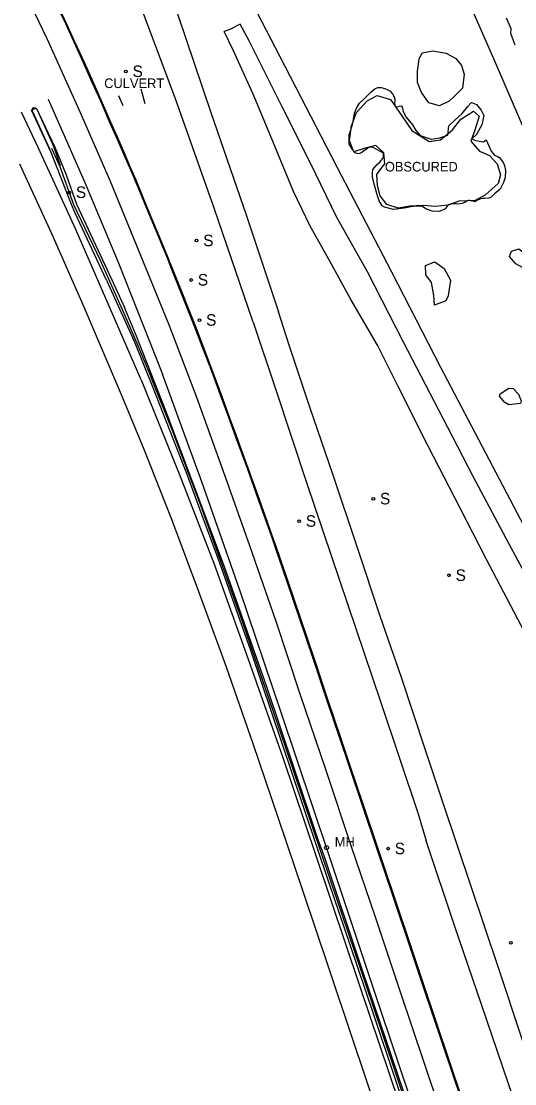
# Model space of a CAD drawing. Extents: x 368532 to 392481, y 10654822 to 10676899.
# Drawn here: x 377470 to 377726, y 10662494 to 10663046 of the extents above; entities that cross this region are included whole.
import ezdxf

# ---------------------------------------------------------------- set-up
doc = ezdxf.new("R2010")
doc.units = 0
for name, color, linetype in [('p_drainage culvert', 7, 'Continuous'), ('p_dtm obscured area', 7, 'Continuous'), ('p_railroad rr control', 7, 'Continuous'), ('p_road - paved curb', 7, 'Continuous'), ('p_road conc barrier', 7, 'Continuous'), ('p_road dirt road', 7, 'Continuous'), ('p_road guard rails', 7, 'Continuous'), ('p_road paint stripe', 7, 'Continuous'), ('p_structure sign', 7, 'Continuous'), ('p_utility manhole', 7, 'Continuous'), ('p_veg woods', 7, 'Continuous')]:
    doc.layers.add(name, color=color, linetype=linetype)

msp = doc.modelspace()

# ---------------------------------------------------------------- linework, layer by layer
at = {"layer": 'p_drainage culvert'}
for p, q in [((377531.8, 10663011.14), (377533.76, 10663003.58)), ((377522.55, 10663002.38), (377520.28, 10663007.6))]:
    msp.add_line(p, q, dxfattribs=at)
at = {"layer": 'p_dtm obscured area'}
msp.add_lwpolyline([(377726.43, 10663033.97), (377724.75, 10663038.16), (377724.08, 10663040.01), (377724.21, 10663042.39), (377723.19, 10663044.85), (377721.77, 10663047.88)], dxfattribs=at)
msp.add_lwpolyline([(377657.26, 10662950.44), (377655.61, 10662953.02), (377654.77, 10662955.59), (377653.71, 10662959.19), (377652.87, 10662962.35), (377652.22, 10662965.49), (377652.22, 10662967.62), (377652.33, 10662969.26), (377653.42, 10662970.48), (377654.62, 10662971.9), (377655.88, 10662972.97), (377656.79, 10662974.12), (377657, 10662974.45), (377657.54, 10662975.12), (377657.98, 10662975.35), (377657.92, 10662977.72), (377652.19, 10662980.83), (377650.5, 10662980.83), (377649.07, 10662979.9), (377647.61, 10662978.94), (377646.16, 10662977.87), (377644.69, 10662977.42), (377643.14, 10662978), (377641.71, 10662979.65), (377640.04, 10662982.53), (377640.13, 10662987.31), (377641.88, 10662993.29), (377642.81, 10662998.58), (377644.22, 10663001.81), (377645.45, 10663003.72), (377647.88, 10663006.02), (377649.29, 10663007.44), (377651.28, 10663009.52), (377653.31, 10663011.15), (377654.92, 10663011.87), (377655.78, 10663011.99), (377656.72, 10663011.87), (377657.92, 10663011.59), (377658.55, 10663011.45), (377660.12, 10663010.75), (377661.45, 10663009.96), (377662.58, 10663008.71), (377663.34, 10663007.44), (377663.83, 10663005.8), (377663.82, 10663004.65), (377663.68, 10663003.88), (377663.78, 10663002.77), (377664.15, 10663001.92), (377665.4, 10663002.09), (377665.99, 10663002.22), (377667.06, 10663002.43), (377667.44, 10663002.15), (377667.76, 10663001.22), (377668.02, 10663000.07), (377668.17, 10662999.53), (377668.5, 10662998.83), (377669.61, 10662996.55), (377672.93, 10662992.45), (377674.66, 10662989.62), (377677, 10662986.99), (377682.7, 10662984.99), (377687.17, 10662985.67), (377691.32, 10662987.09), (377691.86, 10662991.94), (377695.18, 10662995.08), (377698.74, 10662998.45), (377701.77, 10663002.12), (377703.68, 10663004.09), (377706.3, 10663003.02), (377708.75, 10663000.16), (377710.1, 10662997.38), (377708.96, 10662992.44), (377706.21, 10662987.56), (377703.74, 10662985.29), (377705.75, 10662984.34), (377709.9, 10662983.71), (377711.31, 10662984.65), (377712, 10662983.15), (377713.8, 10662978.82), (377715.7, 10662976.54), (377717, 10662976.19), (377718.42, 10662975.33), (377720.09, 10662973.02), (377720.76, 10662971.45), (377721.38, 10662968.86), (377721.2, 10662965.09), (377720.26, 10662962.46), (377718.49, 10662959.1), (377715.68, 10662956.67), (377713.9, 10662954.99), (377712.69, 10662954.38), (377710.48, 10662954.26), (377709.19, 10662954.14), (377708.33, 10662954.03), (377706.48, 10662953.18), (377705.49, 10662952.57), (377704.98, 10662952.59), (377703.83, 10662953.02), (377703.27, 10662953.05), (377702.62, 10662953.17), (377701.85, 10662953.14), (377700.95, 10662952.74), (377700.16, 10662952.16), (377698.84, 10662951.6), (377697.82, 10662951.42), (377697.06, 10662951.25), (377695.93, 10662951.46), (377694.78, 10662951.45), (377693.84, 10662951.45), (377693.13, 10662951.46), (377691.72, 10662950.94), (377691.18, 10662950.59), (377690.81, 10662950.06), (377690.67, 10662949.78), (377689.96, 10662948.85), (377686.99, 10662947.55), (377683.16, 10662947.61), (377680.2, 10662948.7), (377678.03, 10662950.06), (377674.8, 10662950.22), (377672.03, 10662949.89), (377668.72, 10662949.27), (377663.14, 10662948.51), (377658.5, 10662949.8)], close=True, dxfattribs=at)
at = {"layer": 'p_railroad rr control'}
for points in [[(377533.14, 10663389.06), (377560.85, 10663341.04), (377588.79, 10663290.47), (377613.7, 10663243.12), (377634.41, 10663202.3), (377655.63, 10663158.5), (377673.78, 10663119.33), (377695.32, 10663071.97), (377715.09, 10663027.07), (377741.59, 10662965.55)], [(377447.27, 10663322.87), (377465.08, 10663281.81), (377482.07, 10663241.61), (377497.54, 10663201.82), (377506.53, 10663177.13), (377520.96, 10663136.85), (377536.83, 10663091.36), (377550.94, 10663049.62), (377568.16, 10662998.98), (377586.49, 10662945.67), (377603.25, 10662895.25)], [(377590.08, 10662889.98), (377569.68, 10662949.66), (377549.68, 10663006.06), (377531.81, 10663054.07), (377515.57, 10663096.65), (377498.35, 10663138.59), (377483.09, 10663175.15), (377475.05, 10663194.09), (377459.92, 10663228.21), (377440.7, 10663269.48), (377423.08, 10663306.75), (377415.62, 10663322.06)], [(377662.32, 10662915.92), (377633.85, 10662970.55), (377604.16, 10663027.92), (377573.43, 10663087.11), (377541.68, 10663147.47), (377509.84, 10663208.39), (377479.66, 10663266.26), (377460.16, 10663303.76), (377455.02, 10663314.64)], [(377872.51, 10662512.94), (377854.1, 10662547.75), (377833.48, 10662587.51), (377809.12, 10662634), (377784.88, 10662680.38), (377759.49, 10662728.97), (377734.76, 10662776.63), (377712.8, 10662818.59), (377687.78, 10662866.46), (377662.32, 10662915.92)], [(377688.74, 10662640.45), (377679.61, 10662667.96), (377667.24, 10662705.2), (377656.14, 10662737.21), (377644.41, 10662772.65), (377631.82, 10662810.45), (377619.68, 10662845.83), (377608.78, 10662877.94), (377603.25, 10662895.25)], [(377590.08, 10662889.98), (377601.86, 10662854.83), (377617.89, 10662806.63), (377634.98, 10662755.84), (377656.27, 10662692.73), (377675.99, 10662634.43), (377680.14, 10662620.39)], [(377788.33, 10662339.5), (377779.16, 10662370.49), (377766.4, 10662408.93), (377751.86, 10662451.84), (377740.64, 10662485.75), (377729.57, 10662518.37), (377717.5, 10662554.85), (377703.53, 10662596.62), (377688.74, 10662640.45)], [(377857.56, 10662092.99), (377838.98, 10662148.02), (377820.16, 10662203.49), (377802.83, 10662255.08), (377786.31, 10662304.43), (377769.63, 10662354.52), (377752.35, 10662405.57), (377741.43, 10662438), (377734.41, 10662460.71), (377722.68, 10662494.64), (377708.8, 10662535.35), (377695.06, 10662575.82), (377680.14, 10662620.39)]]:
    msp.add_lwpolyline(points, dxfattribs=at)
at = {"layer": 'p_road - paved curb'}
for p, q in [((377492.67, 10663044.93), (377487.72, 10663055.45)), ((377492.81, 10663044.99), (377487.86, 10663055.51)), ((377493.12, 10663045.14), (377488.17, 10663055.66)), ((377497.06, 10663035.53), (377492.67, 10663044.93)), ((377497.2, 10663035.59), (377492.81, 10663044.99)), ((377497.51, 10663035.74), (377493.12, 10663045.14)), ((377502.08, 10663024.73), (377497.2, 10663035.59)), ((377502.4, 10663024.88), (377497.51, 10663035.74)), ((377501.94, 10663024.67), (377497.06, 10663035.53)), ((377506.48, 10663014.59), (377501.94, 10663024.67)), ((377506.62, 10663014.65), (377502.08, 10663024.73)), ((377506.94, 10663014.79), (377502.4, 10663024.88)), ((377510.89, 10663004.75), (377506.48, 10663014.59)), ((377511.03, 10663004.81), (377506.62, 10663014.65)), ((377511.35, 10663004.95), (377506.94, 10663014.79)), ((377515.36, 10662994.42), (377510.89, 10663004.75)), ((377515.5, 10662994.48), (377511.03, 10663004.81)), ((377515.82, 10662994.62), (377511.35, 10663004.95)), ((377474.98, 10663000.1), (377477.41, 10663001.4)), ((377483.87, 10662980.75), (377474.98, 10663000.1)), ((377477.41, 10663001.4), (377486.98, 10662980.96)), ((377519.43, 10662985.2), (377515.36, 10662994.42)), ((377519.57, 10662985.26), (377515.5, 10662994.48)), ((377519.89, 10662985.4), (377515.82, 10662994.62)), ((377485.19, 10662978.18), (377483.87, 10662980.75)), ((377486.98, 10662980.96), (377492.91, 10662966.45)), ((377522.73, 10662977.66), (377519.43, 10662985.2)), ((377522.87, 10662977.72), (377519.57, 10662985.26)), ((377523.19, 10662977.86), (377519.89, 10662985.4)), ((377495.62, 10662951.14), (377485.19, 10662978.18)), ((377525.97, 10662970.11), (377522.73, 10662977.66)), ((377526.11, 10662970.17), (377522.87, 10662977.72)), ((377526.43, 10662970.31), (377523.19, 10662977.86)), ((377528.2, 10662965.05), (377525.97, 10662970.11)), ((377528.34, 10662965.11), (377526.11, 10662970.17)), ((377528.66, 10662965.25), (377526.43, 10662970.31)), ((377492.91, 10662966.45), (377498.24, 10662951.23)), ((377528.97, 10662963.26), (377528.2, 10662965.05)), ((377529.11, 10662963.32), (377528.34, 10662965.11)), ((377529.43, 10662963.46), (377528.66, 10662965.25)), ((377529.6, 10662961.76), (377528.97, 10662963.26)), ((377529.74, 10662961.82), (377529.11, 10662963.32)), ((377530.06, 10662961.95), (377529.43, 10662963.46)), ((377534.83, 10662949.08), (377529.6, 10662961.76)), ((377534.97, 10662949.14), (377529.74, 10662961.82)), ((377535.29, 10662949.27), (377530.06, 10662961.95)), ((377497.57, 10662946.61), (377495.62, 10662951.14)), ((377498.24, 10662951.23), (377516.75, 10662911.94)), ((377538.47, 10662940.32), (377534.83, 10662949.08)), ((377538.61, 10662940.38), (377534.97, 10662949.14)), ((377538.93, 10662940.51), (377535.29, 10662949.27)), ((377513.91, 10662911.82), (377497.57, 10662946.61)), ((377542.25, 10662931.12), (377538.47, 10662940.32)), ((377542.39, 10662931.18), (377538.61, 10662940.38)), ((377542.71, 10662931.31), (377538.93, 10662940.51)), ((377545.52, 10662923.15), (377542.25, 10662931.12)), ((377545.66, 10662923.21), (377542.39, 10662931.18)), ((377545.98, 10662923.34), (377542.71, 10662931.31)), ((377548.46, 10662915.93), (377545.52, 10662923.15)), ((377548.6, 10662915.99), (377545.66, 10662923.21)), ((377548.92, 10662916.12), (377545.98, 10662923.34)), ((377552.05, 10662906.92), (377548.46, 10662915.93)), ((377552.19, 10662906.98), (377548.6, 10662915.99)), ((377552.51, 10662907.1), (377548.92, 10662916.12)), ((377513.91, 10662911.82), (377528.23, 10662880.01)), ((377516.75, 10662911.94), (377523.27, 10662897.64)), ((377556.35, 10662895.98), (377552.05, 10662906.92)), ((377556.49, 10662896.04), (377552.19, 10662906.98)), ((377556.81, 10662896.16), (377552.51, 10662907.1)), ((377529.51, 10662882.6), (377523.27, 10662897.64)), ((377559.8, 10662887.35), (377556.35, 10662895.98)), ((377559.94, 10662887.41), (377556.49, 10662896.04)), ((377560.27, 10662887.53), (377556.81, 10662896.16)), ((377564.03, 10662876.51), (377559.8, 10662887.35)), ((377564.17, 10662876.56), (377559.94, 10662887.41)), ((377564.5, 10662876.69), (377560.27, 10662887.53)), ((377544.69, 10662843.94), (377529.51, 10662882.6)), ((377528.23, 10662880.01), (377537.66, 10662856.8)), ((377568.61, 10662864.5), (377564.03, 10662876.51)), ((377568.75, 10662864.55), (377564.17, 10662876.56)), ((377569.08, 10662864.68), (377564.5, 10662876.69)), ((377573.19, 10662852.07), (377568.61, 10662864.5)), ((377573.33, 10662852.12), (377568.75, 10662864.55)), ((377573.66, 10662852.24), (377569.08, 10662864.68)), ((377537.66, 10662856.8), (377555.94, 10662809.99)), ((377577.43, 10662840.45), (377573.19, 10662852.07)), ((377577.57, 10662840.5), (377573.33, 10662852.12)), ((377577.9, 10662840.62), (377573.66, 10662852.24)), ((377575.21, 10662762.85), (377544.69, 10662843.94)), ((377581.18, 10662830.2), (377577.43, 10662840.45)), ((377581.32, 10662830.25), (377577.57, 10662840.5)), ((377581.65, 10662830.37), (377577.9, 10662840.62)), ((377587.12, 10662813.86), (377581.18, 10662830.2)), ((377587.26, 10662813.91), (377581.32, 10662830.25)), ((377587.59, 10662814.03), (377581.65, 10662830.37)), ((377555.94, 10662809.99), (377563.54, 10662789.68)), ((377592.88, 10662797.63), (377587.12, 10662813.86)), ((377593.02, 10662797.68), (377587.26, 10662813.91)), ((377593.35, 10662797.8), (377587.59, 10662814.03)), ((377599.62, 10662778.86), (377592.88, 10662797.63)), ((377599.76, 10662778.91), (377593.02, 10662797.68)), ((377600.09, 10662779.03), (377593.35, 10662797.8)), ((377563.54, 10662789.68), (377571.75, 10662767.23)), ((377601.6, 10662773.13), (377599.62, 10662778.86)), ((377601.74, 10662773.18), (377599.76, 10662778.91)), ((377602.07, 10662773.29), (377600.09, 10662779.03)), ((377607.83, 10662755.01), (377601.6, 10662773.13)), ((377607.97, 10662755.06), (377601.74, 10662773.18)), ((377608.3, 10662755.17), (377602.07, 10662773.29)), ((377571.75, 10662767.23), (377588.68, 10662719.55)), ((377597.26, 10662700.45), (377575.21, 10662762.85)), ((377617.67, 10662725.87), (377607.83, 10662755.01)), ((377617.81, 10662725.92), (377607.97, 10662755.06)), ((377618.14, 10662726.03), (377608.3, 10662755.17)), ((377621.66, 10662714.12), (377617.67, 10662725.87)), ((377621.8, 10662714.17), (377617.81, 10662725.92)), ((377622.13, 10662714.28), (377618.14, 10662726.03)), ((377588.68, 10662719.55), (377610.44, 10662655.27)), ((377628.68, 10662693.19), (377621.66, 10662714.12)), ((377628.82, 10662693.24), (377621.8, 10662714.17)), ((377629.15, 10662693.35), (377622.13, 10662714.28)), ((377611.68, 10662657.68), (377597.26, 10662700.45)), ((377635.2, 10662673.75), (377628.68, 10662693.19)), ((377635.34, 10662673.8), (377628.82, 10662693.24)), ((377635.67, 10662673.91), (377629.15, 10662693.35)), ((377640.23, 10662658.75), (377635.2, 10662673.75)), ((377640.37, 10662658.8), (377635.34, 10662673.8)), ((377640.7, 10662658.91), (377635.67, 10662673.91)), ((377610.44, 10662655.27), (377629.34, 10662599.02)), ((377623.95, 10662620.96), (377611.68, 10662657.68)), ((377646.82, 10662639.33), (377640.23, 10662658.75)), ((377646.96, 10662639.38), (377640.37, 10662658.8)), ((377647.29, 10662639.49), (377640.7, 10662658.91)), ((377654.98, 10662614.96), (377646.82, 10662639.33)), ((377655.12, 10662615.01), (377646.96, 10662639.38)), ((377655.45, 10662615.12), (377647.29, 10662639.49)), ((377626.98, 10662612.51), (377623.95, 10662620.96)), ((377647.14, 10662552.47), (377626.98, 10662612.51)), ((377662.75, 10662591.88), (377654.98, 10662614.96)), ((377662.89, 10662591.93), (377655.12, 10662615.01)), ((377663.22, 10662592.04), (377655.45, 10662615.12)), ((377629.34, 10662599.02), (377640.16, 10662567.02)), ((377672.08, 10662564.09), (377662.75, 10662591.88)), ((377672.22, 10662564.14), (377662.89, 10662591.93)), ((377672.55, 10662564.25), (377663.22, 10662592.04)), ((377640.16, 10662567.02), (377652.55, 10662530.59)), ((377675.56, 10662553.74), (377672.08, 10662564.09)), ((377675.7, 10662553.79), (377672.22, 10662564.14)), ((377676.03, 10662553.9), (377672.55, 10662564.25)), ((377672.72, 10662477.5), (377647.14, 10662552.47)), ((377679.62, 10662541.67), (377675.56, 10662553.74)), ((377679.76, 10662541.72), (377675.7, 10662553.79)), ((377680.09, 10662541.83), (377676.03, 10662553.9)), ((377683.05, 10662531.49), (377679.62, 10662541.67)), ((377683.19, 10662531.54), (377679.76, 10662541.72)), ((377683.52, 10662531.65), (377680.09, 10662541.83)), ((377652.55, 10662530.59), (377663.76, 10662497.02)), ((377693.96, 10662499), (377683.05, 10662531.49)), ((377694.1, 10662499.05), (377683.19, 10662531.54)), ((377694.43, 10662499.16), (377683.52, 10662531.65)), ((377663.76, 10662497.02), (377676.39, 10662459.41)), ((377698.43, 10662485.72), (377693.96, 10662499)), ((377698.57, 10662485.77), (377694.1, 10662499.05)), ((377698.9, 10662485.88), (377694.43, 10662499.16))]:
    msp.add_line(p, q, dxfattribs=at)
at = {"layer": 'p_road conc barrier'}
for p, q in [((377485.35, 10662980.43), (377489.64, 10662970.87)), ((377489.64, 10662970.87), (377496.72, 10662951.08)), ((377496.72, 10662951.08), (377510.54, 10662922.13)), ((377510.54, 10662922.13), (377522.85, 10662894.63)), ((377522.85, 10662894.63), (377530.2, 10662877.85)), ((377530.2, 10662877.85), (377537.12, 10662861.27)), ((377548, 10662834.03), (377537.12, 10662861.27)), ((377562.92, 10662794.66), (377548, 10662834.03)), ((377584.75, 10662733.81), (377562.92, 10662794.66)), ((377606.96, 10662669.29), (377584.75, 10662733.81)), ((377630.4, 10662599.84), (377606.96, 10662669.29)), ((377652.28, 10662535.04), (377630.4, 10662599.84)), ((377674.04, 10662470.58), (377652.28, 10662535.04))]:
    msp.add_line(p, q, dxfattribs=at)
at = {"layer": 'p_road dirt road'}
for p, q in [((377577.94, 10663042.05), (377574.99, 10663041.03)), ((377583.31, 10663044.85), (377577.94, 10663042.05)), ((377588.21, 10663035.78), (377583.31, 10663044.85)), ((377579.87, 10663031), (377574.99, 10663041.03)), ((377605.17, 10663001.8), (377588.21, 10663035.78)), ((377590.2, 10663008.38), (377579.87, 10663031)), ((377599.36, 10662986.5), (377590.2, 10663008.38)), ((377620.16, 10662972.29), (377605.17, 10663001.8)), ((377611.13, 10662957.92), (377599.36, 10662986.5)), ((377633.41, 10662944.72), (377620.16, 10662972.29)), ((377619.59, 10662940.17), (377611.13, 10662957.92)), ((377649.55, 10662916.04), (377633.41, 10662944.72)), ((377630.93, 10662920.17), (377619.59, 10662940.17)), ((377640.99, 10662901.79), (377630.93, 10662920.17)), ((377668.31, 10662879.62), (377649.55, 10662916.04)), ((377654.7, 10662877.96), (377640.99, 10662901.79)), ((377665.55, 10662856.51), (377654.7, 10662877.96)), ((377691.43, 10662835.15), (377668.31, 10662879.62)), ((377681.07, 10662825.55), (377665.55, 10662856.51)), ((377704.55, 10662809.8), (377691.43, 10662835.15)), ((377697.83, 10662793.34), (377681.07, 10662825.55)), ((377723.1, 10662774.89), (377704.55, 10662809.8)), ((377711.35, 10662766.85), (377697.83, 10662793.34)), ((377737.16, 10662748.87), (377723.1, 10662774.89)), ((377731.33, 10662728.59), (377711.35, 10662766.85))]:
    msp.add_line(p, q, dxfattribs=at)
at = {"layer": 'p_road guard rails'}
for p, q in [((377475.46, 10663000.02), (377475.49, 10663000.82)), ((377475.6, 10662999.28), (377475.46, 10663000.02)), ((377475.49, 10663000.82), (377475.69, 10663001.33)), ((377484.44, 10662979.84), (377475.6, 10662999.28)), ((377475.69, 10663001.33), (377476.22, 10663001.55)), ((377476.22, 10663001.55), (377476.78, 10663001.41)), ((377476.78, 10663001.41), (377477.39, 10663001.03)), ((377477.39, 10663001.03), (377477.78, 10663000.33)), ((377477.78, 10663000.33), (377486.34, 10662981.41)), ((377486.34, 10662981.41), (377489.88, 10662971.43))]:
    msp.add_line(p, q, dxfattribs=at)
at = {"layer": 'p_road paint stripe'}
for p, q in [((377465.28, 10663074.41), (377482.85, 10663037.32)), ((377482.85, 10663037.32), (377499.64, 10663000.08)), ((377483.61, 10663005.91), (377502.55, 10662962.52)), ((377478.31, 10662980.81), (377469.73, 10662999.1)), ((377499.64, 10663000.08), (377515.78, 10662963.18)), ((377497.9, 10662938.17), (377478.31, 10662980.81)), ((377485.67, 10662935.43), (377468.83, 10662972)), ((377502.55, 10662962.52), (377519.9, 10662921.13)), ((377515.78, 10662963.18), (377531.02, 10662926.05)), ((377510.14, 10662910.24), (377497.9, 10662938.17)), ((377502.32, 10662897.82), (377485.67, 10662935.43)), ((377531.02, 10662926.05), (377546.53, 10662888.18)), ((377519.9, 10662921.13), (377543.08, 10662862.86)), ((377531.94, 10662860.03), (377510.14, 10662910.24)), ((377522.25, 10662850.92), (377502.32, 10662897.82)), ((377546.53, 10662888.18), (377560.65, 10662850.93)), ((377531.94, 10662860.03), (377551.63, 10662811.19)), ((377563.52, 10662806.93), (377543.08, 10662862.86)), ((377533.39, 10662823.82), (377522.25, 10662850.92)), ((377560.65, 10662850.93), (377574.54, 10662812.57)), ((377547.8, 10662787.4), (377533.39, 10662823.82)), ((377551.63, 10662811.19), (377569.67, 10662764.62)), ((377574.54, 10662812.57), (377588.31, 10662773.83)), ((377583.21, 10662750.68), (377563.52, 10662806.93)), ((377562.17, 10662749), (377547.8, 10662787.4)), ((377588.31, 10662773.83), (377601.86, 10662734.47)), ((377569.67, 10662764.62), (377587.61, 10662714.83)), ((377576.29, 10662710.59), (377562.17, 10662749)), ((377604.44, 10662687.6), (377583.21, 10662750.68)), ((377601.86, 10662734.47), (377614.47, 10662696.69)), ((377590.11, 10662670.73), (377576.29, 10662710.59)), ((377587.61, 10662714.83), (377605.54, 10662663.69)), ((377614.47, 10662696.69), (377627.68, 10662657.58)), ((377629.49, 10662613.22), (377604.44, 10662687.6)), ((377603.21, 10662632.5), (377590.11, 10662670.73)), ((377605.54, 10662663.69), (377622.93, 10662612.19)), ((377627.68, 10662657.58), (377641, 10662617.98)), ((377616.28, 10662593.43), (377603.21, 10662632.5)), ((377641, 10662617.98), (377653.51, 10662580.93)), ((377622.93, 10662612.19), (377645.67, 10662544.57)), ((377654.69, 10662537.86), (377629.49, 10662613.22)), ((377629.25, 10662554.87), (377616.28, 10662593.43)), ((377653.51, 10662580.93), (377666.32, 10662542.47)), ((377642.12, 10662516.54), (377629.25, 10662554.87)), ((377645.67, 10662544.57), (377666.09, 10662483.95)), ((377666.32, 10662542.47), (377679.21, 10662504.24)), ((377678.19, 10662467.62), (377654.69, 10662537.86)), ((377655.03, 10662478.25), (377642.12, 10662516.54)), ((377679.21, 10662504.24), (377692.26, 10662465.3))]:
    msp.add_line(p, q, dxfattribs=at)
at = {"layer": 'p_structure sign'}
for centre in [(377523.99, 10663020.27), (377494.52, 10662957.4), (377560.71, 10662932.33), (377557.91, 10662911.87), (377562.2, 10662890.98), (377652.61, 10662798.14), (377614.04, 10662786.51), (377691.94, 10662758.35), (377660.29, 10662616.28), (377724.11, 10662567.28)]:
    msp.add_circle(centre, 0.713, dxfattribs=at)
at = {"layer": 'p_utility manhole'}
msp.add_circle((377628.3, 10662616.85), 1.05, dxfattribs=at)
at = {"layer": 'p_veg woods'}
for points in [[(377698.95, 10663011.53), (377694.88, 10663007.39), (377692.11, 10663004.79), (377687, 10663002.41), (377681.52, 10663003.93), (377677.74, 10663009.4), (377675.66, 10663014.58), (377675.6, 10663020.49), (377676.52, 10663026.63), (377677.95, 10663029.87), (377683.56, 10663030.93), (377690.54, 10663029.74), (377695.46, 10663026.93), (377698.45, 10663023.32), (377699.76, 10663018.88)], [(377697, 10662952.92), (377691.46, 10662950.76), (377684.88, 10662950.12), (377678.42, 10662950.58), (377671.57, 10662950.18), (377665.56, 10662949.28), (377659.57, 10662951.07), (377656.12, 10662955.62), (377654.83, 10662960.95), (377654.48, 10662966.78), (377655.91, 10662968.97), (377658.67, 10662972.25), (377658, 10662977.95), (377653.84, 10662981.77), (377648.36, 10662980.35), (377642.5, 10662978.54), (377640.18, 10662984.28), (377641.2, 10662991.97), (377643.85, 10662998.92), (377649.42, 10663004.92), (377654.63, 10663007.84), (377661.52, 10663005.75), (377667.83, 10662996.73), (377672.6, 10662989.64), (377681.62, 10662983.82), (377687.61, 10662984.64), (377693.79, 10662989.86), (377698.03, 10662995.42), (377704.64, 10662999.65), (377707.7, 10662997.07), (377705.47, 10662989.82), (377703.26, 10662984.08), (377707.75, 10662978.78), (377712.98, 10662976.63), (377717.07, 10662972.3), (377718.75, 10662966.56), (377717.57, 10662962.06), (377710.95, 10662956.13), (377705.63, 10662953.12)], [(377734.68, 10662901.17), (377732.79, 10662906.69), (377735.2, 10662910.77), (377734.42, 10662914.28), (377730.19, 10662918.41), (377726.68, 10662920.25), (377723.4, 10662924.03), (377724.45, 10662926.79), (377728.21, 10662928.09), (377733.75, 10662923.92), (377739.91, 10662919.42), (377744, 10662915.34), (377746.81, 10662908.53), (377743.63, 10662901.9)], [(377684.43, 10662898.71), (377684.15, 10662903.81), (377682.78, 10662910.55), (377679.99, 10662914.6), (377679.82, 10662919.38), (377684.65, 10662921.29), (377689.52, 10662917.79), (377692.66, 10662911.74), (377691.6, 10662903.58), (377690.3, 10662900.98)], [(377723.12, 10662846.95), (377720.98, 10662848.11), (377718.29, 10662851.44), (377718.55, 10662852.66), (377723.01, 10662855.58), (377725.35, 10662855.53), (377728.07, 10662852.46), (377729.53, 10662849.06), (377729.08, 10662847.65)]]:
    msp.add_lwpolyline(points, close=True, dxfattribs=at)

# ---------------------------------------------------------------- texts
at = {"layer": 'p_drainage culvert'}
msp.add_text(' CULVERT', height=5, dxfattribs=at).set_placement((377510.83, 10663011.62))
at = {"layer": 'p_dtm obscured area'}
msp.add_text(' OBSCURED', height=5, dxfattribs=at).set_placement((377656.76, 10662968.26))
at = {"layer": 'p_structure sign'}
for p in [(377527.45, 10663017.37), (377497.98, 10662954.5), (377564.17, 10662929.43), (377561.37, 10662908.97), (377565.66, 10662888.09), (377656.07, 10662795.24), (377617.5, 10662783.61), (377695.4, 10662755.45), (377663.75, 10662613.39)]:
    msp.add_text('S', height=6, dxfattribs=at).set_placement(p)
at = {"layer": 'p_utility manhole'}
msp.add_text('MH', height=5, dxfattribs=at).set_placement((377632.57, 10662617.31))

doc.saveas('drawing.dxf')
